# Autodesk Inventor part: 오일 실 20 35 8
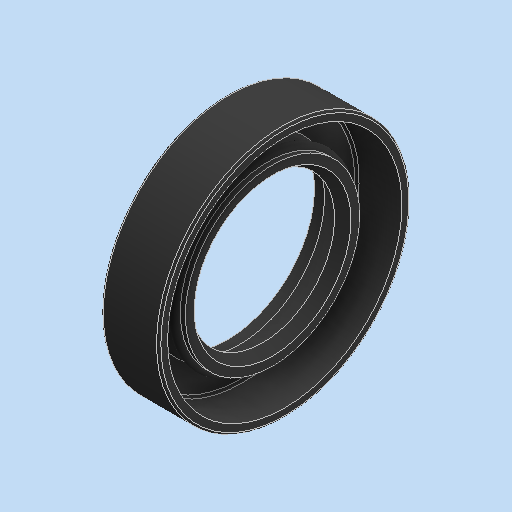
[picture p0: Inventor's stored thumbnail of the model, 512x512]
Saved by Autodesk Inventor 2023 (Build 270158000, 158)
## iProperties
Created: 2026-06
Part Number: 오일 실 20 35 8
Material: 고무
Description: 오일-실
Document SubType Name: Modeling
Designer: home
Density: 0.93 g/cm^3
Appearance: 기본값
Author: jhkim
Sending System: Autodesk Inventor 2027
Preprocessor: ST-DEVELOPER v20.1
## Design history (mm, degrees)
feature "Solid1"
node "솔리드1"
